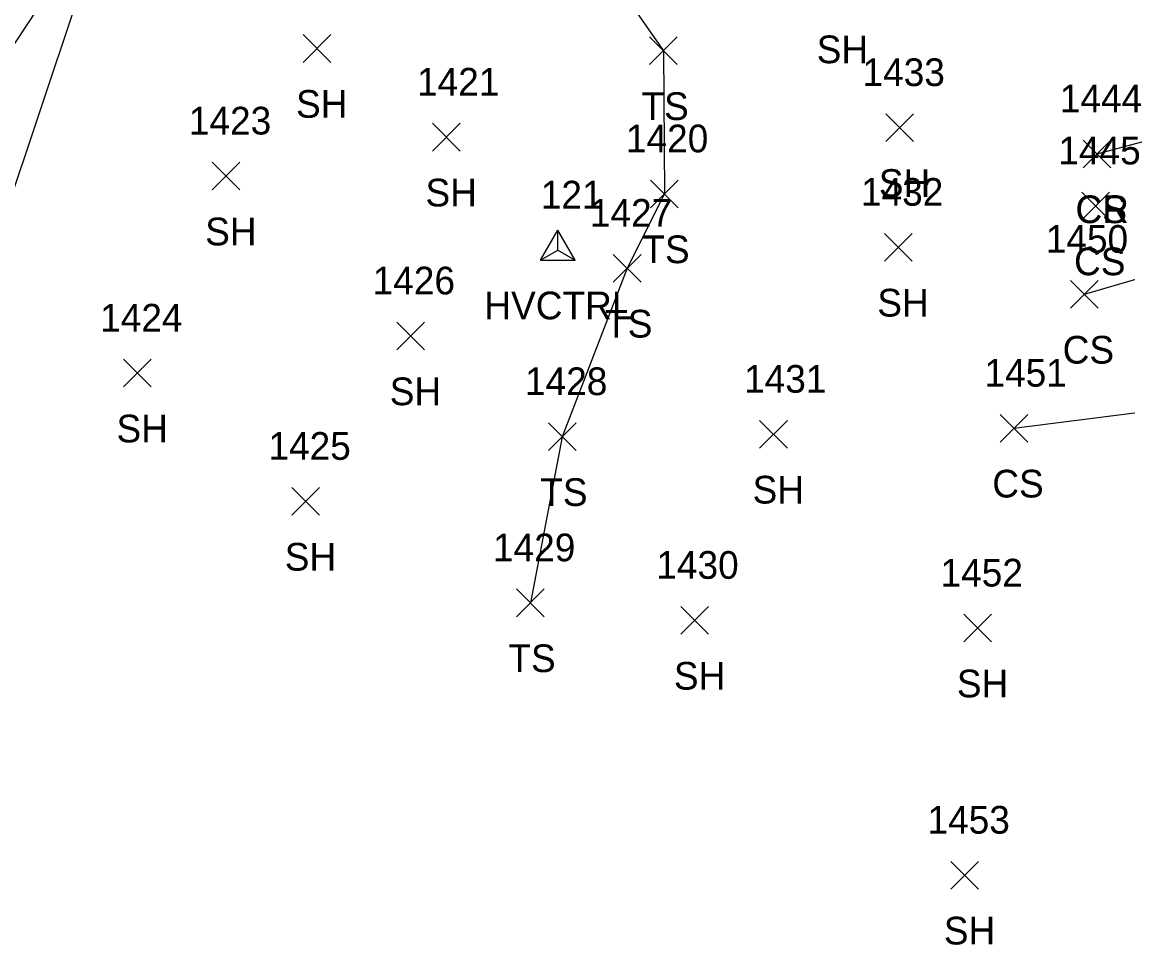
# Model space of a CAD drawing. Extents: x 1485624 to 1495982, y 886445 to 890805.
# Drawn here: x 1495597.7 to 1495677.5, y 890410.5 to 890477.2 of the extents above; entities that cross this region are included whole.
import ezdxf

# ---------------------------------------------------------------- set-up
doc = ezdxf.new("R2010")
doc.units = 0
for name, color, linetype in [('C_A', 7, 'Continuous'), ('C_I', 7, 'Continuous'), ('CPSM', 7, 'Continuous'), ('L_A', 7, 'Continuous'), ('L_I', 7, 'Continuous'), ('L_TIC', 7, 'Continuous'), ('LAWA', 7, 'Continuous'), ('LELB', 7, 'Continuous'), ('P_A', 7, 'Continuous'), ('P_I', 7, 'Continuous'), ('P_TIC', 7, 'Continuous')]:
    doc.layers.add(name, color=color, linetype=linetype)

msp = doc.modelspace()

# ---------------------------------------------------------------- linework, layer by layer
at = {"layer": 'CPSM'}
for p, q in [((1495635.107, 890459.984), (1495636.357, 890462.149)), ((1495637.607, 890459.984), (1495636.357, 890462.149)), ((1495636.357, 890460.705), (1495636.357, 890462.149)), ((1495635.107, 890459.984), (1495636.357, 890460.705)), ((1495636.357, 890460.705), (1495636.357, 890460.705)), ((1495636.357, 890460.705), (1495637.607, 890459.984)), ((1495635.107, 890459.984), (1495637.607, 890459.984))]:
    msp.add_line(p, q, dxfattribs=at)
at = {"layer": 'L_TIC'}
for points in [[(1495617.963, 890474.255), (1495619.963, 890476.255)], [(1495619.963, 890474.255), (1495617.963, 890476.255)], [(1495642.989, 890474.094), (1495644.989, 890476.094)], [(1495644.989, 890474.094), (1495642.989, 890476.094)], [(1495627.315, 890467.855), (1495629.315, 890469.855)], [(1495629.315, 890467.855), (1495627.315, 890469.855)], [(1495660.057, 890468.544), (1495662.057, 890470.544)], [(1495662.057, 890468.544), (1495660.057, 890470.544)], [(1495674.31, 890466.649), (1495676.31, 890468.649)], [(1495676.31, 890466.649), (1495674.31, 890468.649)], [(1495611.402, 890465.047), (1495613.402, 890467.047)], [(1495613.402, 890465.047), (1495611.402, 890467.047)], [(1495643.057, 890463.76), (1495645.057, 890465.76)], [(1495645.057, 890463.76), (1495643.057, 890465.76)], [(1495674.202, 890462.89), (1495676.202, 890464.89)], [(1495676.202, 890462.89), (1495674.202, 890464.89)], [(1495659.945, 890459.906), (1495661.945, 890461.906)], [(1495661.945, 890459.906), (1495659.945, 890461.906)], [(1495640.367, 890458.39), (1495642.367, 890460.39)], [(1495642.367, 890458.39), (1495640.367, 890460.39)], [(1495673.378, 890456.509), (1495675.378, 890458.509)], [(1495675.378, 890456.509), (1495673.378, 890458.509)], [(1495624.732, 890453.506), (1495626.732, 890455.506)], [(1495626.732, 890453.506), (1495624.732, 890455.506)], [(1495604.997, 890450.82), (1495606.997, 890452.82)], [(1495606.997, 890450.82), (1495604.997, 890452.82)], [(1495650.936, 890446.407), (1495652.936, 890448.407)], [(1495652.936, 890446.407), (1495650.936, 890448.407)], [(1495668.297, 890446.844), (1495670.297, 890448.844)], [(1495670.297, 890446.844), (1495668.297, 890448.844)], [(1495635.681, 890446.233), (1495637.681, 890448.233)], [(1495637.681, 890446.233), (1495635.681, 890448.233)], [(1495617.15, 890441.563), (1495619.15, 890443.563)], [(1495619.15, 890441.563), (1495617.15, 890443.563)], [(1495633.377, 890434.238), (1495635.377, 890436.238)], [(1495635.377, 890434.238), (1495633.377, 890436.238)], [(1495645.253, 890432.973), (1495647.253, 890434.973)], [(1495647.253, 890432.973), (1495645.253, 890434.973)], [(1495665.691, 890432.415), (1495667.691, 890434.415)], [(1495667.691, 890432.415), (1495665.691, 890434.415)], [(1495664.751, 890414.576), (1495666.751, 890416.576)], [(1495666.751, 890414.576), (1495664.751, 890416.576)]]:
    msp.add_lwpolyline(points, dxfattribs=at)
at = {"layer": 'LAWA'}
msp.add_lwpolyline([(1495593.767, 890455.288), (1495604.157, 890486.253), (1495624.555, 890513.669), (1495629.053, 890516.165), (1495630.207, 890519.388)], dxfattribs=at)
at = {"layer": 'LELB'}
for points in [[(1495644.282, 890509.681), (1495663.889, 890496.334), (1495679.643, 890489.96), (1495689.212, 890481.509), (1495701.426, 890473.385), (1495703.964, 890466.127), (1495674.378, 890457.509)], [(1495585.725, 890458.372), (1495604.157, 890486.253), (1495622.816, 890500.588)], [(1495622.816, 890500.588), (1495632.932, 890490.925), (1495643.989, 890475.094), (1495644.057, 890464.76), (1495641.367, 890459.39), (1495636.681, 890447.233), (1495634.377, 890435.238)], [(1495675.31, 890467.649), (1495689.1, 890471.354), (1495701.426, 890473.385)], [(1495669.297, 890447.844), (1495694.298, 890451.024)]]:
    msp.add_lwpolyline(points, dxfattribs=at)
at = {"layer": 'P_TIC'}
for points in [[(1495674.31, 890466.649), (1495676.31, 890468.649)], [(1495676.31, 890466.649), (1495674.31, 890468.649)]]:
    msp.add_lwpolyline(points, dxfattribs=at)

# ---------------------------------------------------------------- texts
at = {"layer": 'C_A'}
msp.add_text('HVCTRL', height=2, dxfattribs=at).set_placement((1495631.05, 890455.705))
at = {"layer": 'C_I'}
msp.add_text('121', height=2, dxfattribs=at).set_placement((1495635.129, 890463.705))
at = {"layer": 'L_A'}
for s, p in [('SH', (1495655.056, 890474.194)), ('SH', (1495617.451, 890470.255)), ('TS', (1495642.399, 890470.094)), ('SH', (1495626.803, 890463.855)), ('SH', (1495659.545, 890464.544)), ('CS', (1495673.751, 890462.649)), ('SH', (1495610.891, 890461.047)), ('TS', (1495642.466, 890459.76)), ('CS', (1495673.643, 890458.89)), ('SH', (1495659.433, 890455.906)), ('TS', (1495639.777, 890454.39)), ('CS', (1495672.819, 890452.509)), ('SH', (1495624.22, 890449.506)), ('SH', (1495604.486, 890446.82)), ('TS', (1495635.091, 890442.233)), ('SH', (1495650.424, 890442.407)), ('CS', (1495667.738, 890442.844)), ('SH', (1495616.638, 890437.563)), ('TS', (1495632.787, 890430.238)), ('SH', (1495644.742, 890428.973)), ('SH', (1495665.179, 890428.415)), ('SH', (1495664.239, 890410.576))]:
    msp.add_text(s, height=2, dxfattribs=at).set_placement(p)
at = {"layer": 'L_I'}
for s, p in [('1421', (1495626.19, 890471.855)), ('1433', (1495658.364, 890472.544)), ('1444', (1495672.617, 890470.649)), ('1423', (1495609.71, 890469.047)), ('1420', (1495641.278, 890467.76)), ('1445', (1495672.509, 890466.89)), ('1432', (1495658.253, 890463.906)), ('1427', (1495638.675, 890462.39)), ('1450', (1495671.598, 890460.509)), ('1426', (1495622.984, 890457.506)), ('1424', (1495603.305, 890454.82)), ('1428', (1495633.988, 890450.233)), ('1431', (1495649.81, 890450.407)), ('1451', (1495667.171, 890450.844)), ('1425', (1495615.457, 890445.563)), ('1429', (1495631.677, 890438.238)), ('1430', (1495643.474, 890436.973)), ('1452', (1495663.998, 890436.415)), ('1453', (1495663.058, 890418.576))]:
    msp.add_text(s, height=2, dxfattribs=at).set_placement(p)
at = {"layer": 'P_A'}
msp.add_text('CR', height=2, dxfattribs=at).set_placement((1495673.743, 890462.649))
at = {"layer": 'P_I'}
msp.add_text('1444', height=2, dxfattribs=at).set_placement((1495672.617, 890470.649))

doc.saveas('drawing.dxf')
